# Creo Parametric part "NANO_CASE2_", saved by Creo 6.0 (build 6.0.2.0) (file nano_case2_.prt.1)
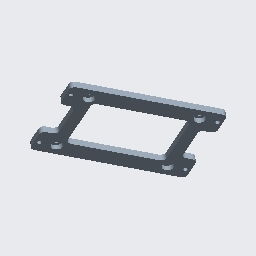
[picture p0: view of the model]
Units: Inch lbm Second (Pro/E Default); INCH, POUND, SECS

Created from: INLBS_PART_SOLID.PRT

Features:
  1. datum plane "RIGHT"
  2. datum plane "TOP"
  3. datum plane "FRONT"
  4. coordinate system
  5. sketch "Sketch 1"
  6. extrusion "Extrude 1"
  7. sketch "Sketch 2"
  8. extruded cut "Extrude 2"
  9. sketch "Sketch 3"
  10. extruded cut "Extrude 3"
  11. sketch "Sketch 4"
  12. extrusion "Extrude 4"
  13. round "Round 1"
  14. sketch "Sketch 5"
  15. extruded cut "Extrude 5"
  16. sketch "Sketch 6"
  17. extruded cut "Extrude 6"
  18. round "Round 2"

Surfaces: 28 cylinder, 18 plane, 8 torus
